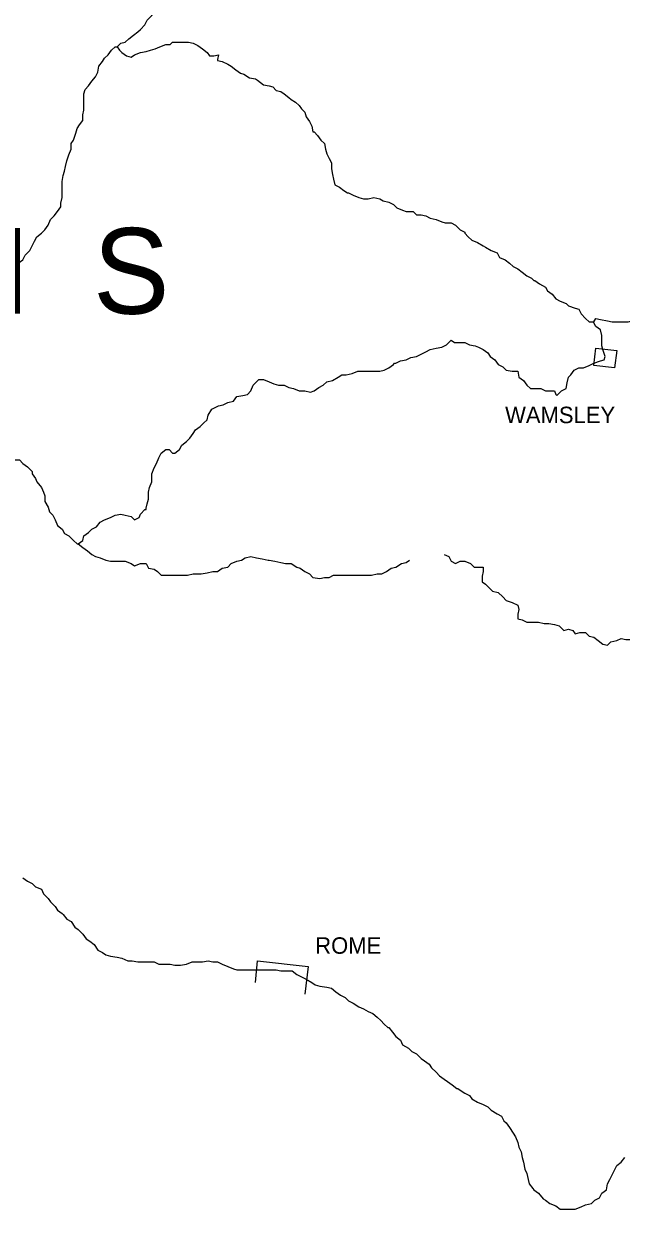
# Model space of a CAD drawing. Extents: x 0 to 34, y 0 to 22.
# Drawn here: x 4.368 to 5.076, y 15.791 to 17.195 of the extents above; entities that cross this region are included whole.
import ezdxf

# ---------------------------------------------------------------- set-up
doc = ezdxf.new("R2010")
doc.units = 0
doc.layers.add('Default', color=7, linetype='Continuous')
doc.layers.add('TR_Turning_Path1', color=7, linetype='Continuous')

msp = doc.modelspace()

# ---------------------------------------------------------------- linework, layer by layer
at = {"layer": 'Default'}
for points in [[(4.512, 17.194), (4.5148, 17.1994), (4.5202, 17.2049), (4.5229, 17.209), (4.527, 17.2144), (4.5311, 17.2199), (4.5352, 17.2253), (4.5393, 17.2294), (4.542, 17.2363), (4.5475, 17.2403), (4.5502, 17.2458), (4.5543, 17.2513), (4.557, 17.2553), (4.5625, 17.2622), (4.5638, 17.2662), (4.5666, 17.2717), (4.5693, 17.2758), (4.5693, 17.2772)], [(4.4793, 17.1681), (4.4834, 17.1722), (4.4888, 17.1735), (4.4929, 17.1776), (4.4984, 17.1817), (4.5038, 17.1858), (4.5066, 17.1885), (4.512, 17.194), (4.512, 17.194)], [(4.4125, 16.9827), (4.4139, 16.9895), (4.4139, 16.9949), (4.4139, 17.0017), (4.4139, 17.0086), (4.4152, 17.0154), (4.4166, 17.0208), (4.4179, 17.0263), (4.4193, 17.0331), (4.422, 17.0399), (4.4248, 17.0467), (4.4248, 17.0536), (4.4275, 17.0576), (4.4302, 17.0658), (4.4316, 17.0713), (4.4343, 17.0754), (4.4384, 17.0808), (4.4384, 17.0876), (4.4398, 17.0931), (4.4398, 17.0999), (4.4398, 17.1067), (4.4398, 17.1122), (4.4411, 17.1176), (4.4452, 17.1217), (4.4493, 17.1272), (4.4534, 17.1326), (4.4561, 17.1381), (4.4575, 17.1449), (4.4616, 17.1504), (4.4643, 17.1544), (4.4684, 17.1585), (4.4725, 17.164), (4.4766, 17.1681), (4.4766, 17.1681), (4.4793, 17.1681)], [(4.4793, 17.1681), (4.482, 17.164), (4.4848, 17.1613)], [(4.4848, 17.1613), (4.4902, 17.1572), (4.4957, 17.1558), (4.4998, 17.1585), (4.5066, 17.1613), (4.5134, 17.1626), (4.5188, 17.164), (4.5243, 17.1654), (4.5297, 17.1681), (4.5366, 17.1708), (4.542, 17.1708), (4.5447, 17.1735), (4.5516, 17.1735), (4.557, 17.1735), (4.5638, 17.1735), (4.5693, 17.1722), (4.5747, 17.1694), (4.5802, 17.1654), (4.5856, 17.1613), (4.5884, 17.1572), (4.5938, 17.1572), (4.5993, 17.1585), (4.5979, 17.1531), (4.5979, 17.1517)], [(4.5979, 17.1517), (4.6034, 17.1504), (4.6102, 17.1476), (4.6143, 17.1449), (4.6197, 17.1408), (4.6252, 17.1367), (4.6293, 17.1354), (4.6361, 17.1313), (4.6429, 17.1299), (4.6456, 17.1285), (4.6525, 17.1231), (4.6593, 17.1217), (4.6634, 17.1204), (4.6675, 17.1163), (4.6729, 17.1149), (4.677, 17.1122), (4.6825, 17.1081), (4.6852, 17.1054), (4.6906, 17.1026), (4.6947, 17.0985), (4.6974, 17.0945), (4.7015, 17.0904), (4.7029, 17.0849), (4.707, 17.0795), (4.7097, 17.074), (4.7111, 17.0672), (4.7124, 17.0672)], [(4.7124, 17.0672), (4.7165, 17.0631), (4.7206, 17.0576), (4.7247, 17.0536), (4.7261, 17.0467), (4.7274, 17.0413), (4.7302, 17.0358), (4.7329, 17.0304), (4.7329, 17.0236), (4.7343, 17.0167), (4.7356, 17.0113), (4.737, 17.0045), (4.7424, 17.0017), (4.7479, 16.9977), (4.752, 16.9949), (4.752, 16.9949), (4.7533, 16.9949)], [(4.7533, 16.9949), (4.7588, 16.9922), (4.7656, 16.9895), (4.7711, 16.9881), (4.7765, 16.9881), (4.7833, 16.9895), (4.7902, 16.9881), (4.7943, 16.9854), (4.8011, 16.984), (4.8065, 16.9813), (4.8106, 16.9772), (4.8174, 16.9745), (4.8215, 16.9731), (4.8297, 16.9731), (4.8338, 16.969), (4.8392, 16.969), (4.8447, 16.9677), (4.8502, 16.9649), (4.857, 16.9636), (4.8638, 16.9608), (4.8679, 16.9595), (4.8747, 16.9595), (4.8801, 16.9568), (4.8856, 16.9513), (4.8911, 16.9486), (4.8911, 16.9472)], [(4.3321, 16.9022), (4.3389, 16.9063), (4.343, 16.9077), (4.3511, 16.9077), (4.3566, 16.9077), (4.362, 16.9118), (4.3675, 16.9158), (4.3702, 16.9213), (4.3757, 16.9268), (4.3784, 16.9322), (4.3811, 16.9377), (4.3839, 16.9431), (4.3893, 16.9472), (4.3934, 16.9513), (4.3975, 16.9568), (4.4002, 16.9636), (4.4043, 16.9677), (4.4084, 16.9731), (4.4125, 16.9786), (4.4125, 16.9827)], [(4.8911, 16.9472), (4.8951, 16.9431), (4.8992, 16.939), (4.9061, 16.9363), (4.9129, 16.9322), (4.9156, 16.9308), (4.9224, 16.9268), (4.9292, 16.924), (4.932, 16.9186), (4.9388, 16.9158), (4.9442, 16.9118), (4.9483, 16.9077), (4.9538, 16.9049), (4.9592, 16.9009), (4.9647, 16.8968), (4.9701, 16.894), (4.9729, 16.8913), (4.9742, 16.8913)], [(4.9742, 16.8913), (4.9797, 16.8872), (4.9865, 16.8831), (4.9892, 16.879), (4.9947, 16.8749), (4.9988, 16.8695), (5.0042, 16.8668), (5.011, 16.864), (5.0138, 16.8613), (5.0219, 16.8586), (5.026, 16.8572), (5.0288, 16.8518), (5.0342, 16.8463), (5.0383, 16.8422), (5.0438, 16.8422)], [(5.0001, 16.755), (5.0056, 16.7604), (5.011, 16.7631), (5.0124, 16.77), (5.0138, 16.7768), (5.0165, 16.7795), (5.0206, 16.785), (5.026, 16.7877), (5.0315, 16.7877), (5.0383, 16.7904), (5.0438, 16.7931), (5.0519, 16.7959), (5.056, 16.7972), (5.0574, 16.8013), (5.0547, 16.8095), (5.0533, 16.8136), (5.0533, 16.8204), (5.0533, 16.8259), (5.0519, 16.8327), (5.0465, 16.8368), (5.0438, 16.8409), (5.0438, 16.8422), (5.0438, 16.8422)], [(5.0438, 16.8422), (5.0465, 16.8463), (5.0519, 16.845), (5.0601, 16.8436), (5.0656, 16.8422), (5.071, 16.8422), (5.0778, 16.8422), (5.0847, 16.8422), (5.0888, 16.8436), (5.0888, 16.8436)], [(4.8092, 16.7931), (4.8147, 16.7959), (4.8215, 16.7972), (4.827, 16.8), (4.8338, 16.8013), (4.8392, 16.804), (4.8447, 16.8068), (4.8502, 16.8095), (4.857, 16.8109), (4.8638, 16.8122), (4.8692, 16.815), (4.8747, 16.8204), (4.8788, 16.8177), (4.8801, 16.8177)], [(4.8801, 16.8177), (4.8842, 16.8177), (4.8911, 16.8177), (4.8965, 16.815), (4.9033, 16.8136), (4.9074, 16.8122), (4.9129, 16.8095), (4.9183, 16.8054), (4.9211, 16.8013), (4.9211, 16.8013)], [(5.0465, 16.8109), (5.071, 16.8081), (5.0683, 16.7877), (5.0438, 16.7904), (5.0465, 16.8109)], [(4.9211, 16.8013), (4.9265, 16.7972), (4.9306, 16.7918), (4.936, 16.7891), (4.9401, 16.785), (4.947, 16.7836), (4.9538, 16.7836), (4.9551, 16.7768), (4.9606, 16.7727), (4.9647, 16.7672), (4.9688, 16.7631), (4.9729, 16.7631), (4.981, 16.7631), (4.9865, 16.7604), (4.9919, 16.7604), (4.9974, 16.7604), (4.9988, 16.7563), (5.0001, 16.755)], [(4.647, 16.7741), (4.6525, 16.7741), (4.6593, 16.7713), (4.6647, 16.7686), (4.6702, 16.7672), (4.677, 16.7672), (4.6825, 16.7645), (4.6879, 16.7631), (4.6947, 16.7604), (4.7015, 16.7604), (4.7084, 16.7591), (4.7124, 16.7604), (4.7179, 16.7645), (4.7234, 16.7672), (4.7274, 16.7713), (4.7343, 16.7727), (4.7411, 16.7768), (4.7452, 16.7795), (4.7506, 16.7795), (4.7574, 16.7809), (4.7643, 16.7836), (4.7697, 16.7836), (4.7765, 16.7836), (4.7833, 16.7836), (4.7902, 16.7836), (4.7956, 16.785), (4.8011, 16.7877), (4.8065, 16.7918), (4.8079, 16.7931), (4.8092, 16.7931)], [(4.5938, 16.74), (4.5993, 16.7427), (4.6047, 16.7441), (4.6102, 16.7468), (4.617, 16.7481), (4.6211, 16.7536), (4.6279, 16.755), (4.6334, 16.7563), (4.6375, 16.7604), (4.6402, 16.7672), (4.6443, 16.7713), (4.647, 16.7741)], [(4.5475, 16.6868), (4.5529, 16.6909), (4.5557, 16.6963), (4.5611, 16.7004), (4.5652, 16.7045), (4.5693, 16.71), (4.572, 16.7141), (4.5775, 16.7182), (4.5816, 16.7222), (4.5856, 16.7263), (4.587, 16.7318), (4.5911, 16.7386), (4.5938, 16.74)], [(4.5134, 16.6214), (4.5148, 16.6268), (4.5161, 16.6323), (4.5161, 16.6404), (4.5175, 16.6459), (4.5202, 16.6527), (4.5202, 16.6568), (4.5202, 16.6623), (4.5229, 16.6691), (4.5257, 16.6745), (4.5284, 16.6813), (4.5311, 16.6868), (4.5366, 16.6909), (4.5407, 16.6909), (4.5447, 16.6868), (4.5475, 16.6868), (4.5475, 16.6868)], [(4.2775, 16.6623), (4.283, 16.6623), (4.2911, 16.6623), (4.2966, 16.6623), (4.3021, 16.6609), (4.3089, 16.6623), (4.3157, 16.665), (4.3211, 16.6677), (4.3266, 16.6704), (4.3321, 16.6732), (4.3389, 16.6745), (4.3443, 16.6773), (4.3511, 16.6786), (4.358, 16.6786), (4.3634, 16.6786), (4.3675, 16.6745), (4.373, 16.6704), (4.3784, 16.665), (4.3784, 16.6623)], [(4.3784, 16.6623), (4.3825, 16.6568), (4.3839, 16.6527), (4.3893, 16.6459), (4.392, 16.6404), (4.3934, 16.6363), (4.3934, 16.6295), (4.3975, 16.6227), (4.3989, 16.6173), (4.403, 16.6132), (4.4057, 16.6077), (4.4084, 16.6009), (4.4139, 16.5968), (4.4166, 16.5914), (4.422, 16.5886), (4.4275, 16.5832), (4.4316, 16.5791), (4.4329, 16.5791), (4.4329, 16.5791)], [(4.4329, 16.5791), (4.4384, 16.5832), (4.4398, 16.5886), (4.4452, 16.5927), (4.4493, 16.5968), (4.4548, 16.5995), (4.4589, 16.605), (4.4643, 16.6077), (4.4711, 16.6104), (4.4766, 16.6132), (4.4834, 16.6145), (4.4888, 16.6132), (4.4957, 16.6118), (4.4998, 16.6077), (4.5052, 16.6104), (4.5066, 16.6145), (4.512, 16.62), (4.5134, 16.62), (4.5134, 16.6214)], [(4.4329, 16.5791), (4.4384, 16.575), (4.4439, 16.5709), (4.4493, 16.5668), (4.4534, 16.5641), (4.4589, 16.5627), (4.4657, 16.56), (4.4711, 16.5586), (4.4766, 16.5586), (4.4834, 16.5586), (4.4888, 16.5586), (4.4957, 16.5559), (4.4998, 16.5532), (4.5066, 16.5559), (4.5134, 16.5559), (4.5161, 16.5505), (4.5229, 16.5491), (4.527, 16.5464), (4.5311, 16.5423), (4.5379, 16.5423), (4.5447, 16.5423), (4.5502, 16.5423), (4.557, 16.5423), (4.5625, 16.5423), (4.5693, 16.5436), (4.572, 16.5436)], [(4.572, 16.5436), (4.5788, 16.5436), (4.5856, 16.545), (4.5925, 16.5464), (4.5979, 16.5464), (4.6034, 16.5505), (4.6102, 16.5518), (4.6143, 16.5559), (4.6211, 16.5586), (4.6266, 16.56), (4.6306, 16.5627), (4.6375, 16.5641), (4.6443, 16.5627), (4.6511, 16.5614), (4.6579, 16.56), (4.6593, 16.56)], [(4.6593, 16.56), (4.6661, 16.5586), (4.6729, 16.5573), (4.6784, 16.5559), (4.6852, 16.5559), (4.692, 16.5518), (4.6961, 16.5505), (4.7015, 16.5464), (4.707, 16.5436), (4.7111, 16.5395), (4.7193, 16.5382), (4.7247, 16.5395), (4.7302, 16.5395), (4.7356, 16.5423), (4.7356, 16.5423), (4.7356, 16.5423)], [(4.7356, 16.5423), (4.7411, 16.5423), (4.7493, 16.5423), (4.7561, 16.5423), (4.7615, 16.5423), (4.767, 16.5423), (4.7738, 16.5423), (4.7806, 16.5423), (4.7874, 16.5436), (4.7929, 16.5436), (4.7983, 16.5464), (4.8038, 16.5505), (4.8092, 16.5518), (4.8161, 16.5559), (4.8215, 16.5573), (4.8256, 16.56), (4.8256, 16.56)], [(4.8665, 16.5668), (4.872, 16.5641), (4.8747, 16.5586), (4.8801, 16.5559), (4.8856, 16.5586), (4.8911, 16.5586), (4.8979, 16.5559), (4.902, 16.5518), (4.9074, 16.5518), (4.9129, 16.5518), (4.9129, 16.5464), (4.9115, 16.5409), (4.9115, 16.5355), (4.9115, 16.5341)], [(4.9115, 16.5341), (4.9156, 16.5314), (4.9211, 16.5259), (4.9238, 16.5232), (4.9306, 16.5218), (4.936, 16.5164), (4.9401, 16.5123), (4.947, 16.5096), (4.9538, 16.5068), (4.9551, 16.5014), (4.9538, 16.4959), (4.9538, 16.4905), (4.9592, 16.4891), (4.9592, 16.4891)], [(4.9592, 16.4891), (4.9647, 16.4864), (4.9715, 16.4864), (4.9783, 16.4864), (4.9851, 16.485), (4.9906, 16.485), (4.9974, 16.4836), (5.0029, 16.4823), (5.0083, 16.4768), (5.0138, 16.4782), (5.0192, 16.4768), (5.0219, 16.4727), (5.0274, 16.4741), (5.0288, 16.4741)], [(5.0288, 16.4741), (5.0342, 16.4741), (5.0383, 16.47), (5.0438, 16.4686), (5.0492, 16.4646), (5.0547, 16.4605), (5.0601, 16.4591), (5.0642, 16.4632), (5.071, 16.4646), (5.0765, 16.4673), (5.0819, 16.4659), (5.0847, 16.4659), (5.0874, 16.4659)], [(4.3675, 16.1837), (4.373, 16.1796), (4.3784, 16.1769), (4.3825, 16.1728), (4.3893, 16.1701), (4.392, 16.1646), (4.3975, 16.1592), (4.4002, 16.1551), (4.4057, 16.1496), (4.4084, 16.1455), (4.4139, 16.1414), (4.4139, 16.1414), (4.4152, 16.1401)], [(4.4152, 16.1401), (4.4193, 16.1346), (4.4248, 16.1319), (4.4289, 16.1251), (4.4329, 16.1223), (4.4384, 16.1169), (4.4425, 16.1114), (4.4466, 16.1087), (4.452, 16.1046), (4.4561, 16.0978), (4.4616, 16.0951), (4.4657, 16.0923), (4.4711, 16.091), (4.4793, 16.0896), (4.4848, 16.0883), (4.4916, 16.0855), (4.497, 16.0855), (4.5038, 16.0842), (4.5093, 16.0842), (4.5161, 16.0842), (4.5229, 16.0842), (4.5284, 16.0814), (4.5366, 16.0814), (4.542, 16.0814), (4.5475, 16.0801), (4.5543, 16.0801), (4.5611, 16.0814), (4.5679, 16.0842), (4.572, 16.0842), (4.5802, 16.0842), (4.587, 16.0855), (4.5925, 16.0842), (4.5979, 16.0842), (4.6034, 16.0814), (4.6102, 16.0787), (4.617, 16.076), (4.6211, 16.0746), (4.6279, 16.0746), (4.6347, 16.0746), (4.6429, 16.0746), (4.647, 16.0746), (4.6538, 16.0746), (4.6606, 16.0746), (4.6675, 16.0746), (4.6729, 16.0733), (4.6784, 16.0733), (4.6852, 16.0733), (4.6865, 16.0733)], [(4.6429, 16.0596), (4.6456, 16.0855), (4.7056, 16.0787), (4.7015, 16.046)], [(4.6865, 16.0733), (4.692, 16.0692), (4.6974, 16.0664), (4.7029, 16.0637), (4.7097, 16.0596), (4.7138, 16.0569), (4.7193, 16.0555), (4.7274, 16.0542), (4.7329, 16.0528), (4.7384, 16.0487), (4.7438, 16.0446), (4.7493, 16.0419), (4.7533, 16.0378), (4.7588, 16.0351), (4.7656, 16.031), (4.7711, 16.0283), (4.7765, 16.0255), (4.782, 16.0228), (4.7874, 16.0187), (4.7915, 16.0146), (4.7956, 16.0105), (4.7997, 16.0064), (4.7997, 16.0064), (4.8011, 16.0064)], [(4.8011, 16.0064), (4.8052, 16.001), (4.8092, 15.9955), (4.8147, 15.9915), (4.8174, 15.986), (4.8242, 15.9819), (4.8283, 15.9778), (4.8338, 15.9751), (4.8392, 15.9696), (4.8433, 15.9669), (4.8488, 15.9628), (4.8515, 15.9587), (4.857, 15.9533), (4.8611, 15.9492), (4.8665, 15.9451), (4.8706, 15.9424), (4.8761, 15.9383), (4.8815, 15.9342), (4.8829, 15.9342), (4.8842, 15.9328)], [(4.8842, 15.9328), (4.8911, 15.9287), (4.8965, 15.926), (4.8992, 15.9219), (4.9061, 15.9178), (4.9129, 15.9151), (4.9183, 15.9124), (4.9224, 15.9083), (4.9292, 15.9042), (4.9347, 15.9015), (4.9374, 15.896), (4.9401, 15.8933), (4.9442, 15.8878), (4.9483, 15.881), (4.951, 15.8769), (4.9538, 15.8701), (4.9551, 15.8647), (4.9579, 15.8592), (4.9592, 15.8524), (4.9606, 15.8469), (4.962, 15.8387), (4.9647, 15.8333), (4.966, 15.8265), (4.9674, 15.821), (4.9715, 15.8156), (4.9729, 15.8142), (4.9729, 15.8142)], [(4.9729, 15.8142), (4.9783, 15.8101), (4.9838, 15.8033), (4.9865, 15.8019), (4.9919, 15.7978), (4.9988, 15.7951), (5.0042, 15.791), (5.011, 15.791), (5.0165, 15.791), (5.0219, 15.791), (5.0288, 15.7938), (5.0342, 15.7965), (5.041, 15.7978), (5.0451, 15.8019), (5.0506, 15.8047), (5.0533, 15.8101), (5.0588, 15.8142), (5.0601, 15.821), (5.0628, 15.8265), (5.0656, 15.8319), (5.0683, 15.8374), (5.071, 15.8428), (5.0765, 15.8469), (5.0806, 15.8524)]]:
    msp.add_lwpolyline(points, dxfattribs=at)

# ---------------------------------------------------------------- texts
for s, p in [('WAMSLEY', (4.9388, 16.7222)), ('ROME', (4.7138, 16.0937))]:
    msp.add_text(s, height=0.0195, dxfattribs=at).set_placement(p)
at = {"layer": 'TR_Turning_Path1'}
msp.add_text('A  D  A  M  S', height=0.101489, dxfattribs=at).set_placement((3.7568, 16.8518))

doc.saveas('drawing.dxf')
